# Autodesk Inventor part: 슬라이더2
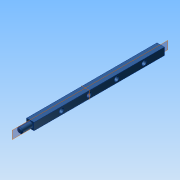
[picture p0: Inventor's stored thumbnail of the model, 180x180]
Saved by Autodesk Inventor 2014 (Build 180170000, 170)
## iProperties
Company: 한국ATC센터
Created: 2015-04
Part Number: 슬라이더2
Document SubType Name: Modeling
Designer: KYOUNG IL JANG
Density: 7.85 g/cm^3
Material: 강
Appearance: 하늘색 짙음
Author: KYOUNG IL JANG
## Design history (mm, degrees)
sketch "스케치3"
  geometry: L1 (4, 142)-(-4, 142); L2 (-4, 142)-(-4, 0); L3 (-4, 0)-(4, 0); L4 (4, 0)-(4, 142); 3 further points
  constraints: 8 end point, 2 coincident, 2 parallel, 1 horizontal, 1 midpoint, 1 perpendicular
  dimensions: "d5" = 8 distance of L1.start L1.end; "d6" = 142 distance of L1.end L2.end
extrude "돌출3" new body sketch "스케치3" stored distance "d7" = 8; taper "d8" = 0 deg
sketch "스케치4"
  geometry: L1 (8, 0)-(0, 0) reference; 3 further points
  constraints: 1 midpoint, 1 vertical alignment
  dimensions: "d9" = 30 distance of point (4, 30) point (4, 0)
hole "구멍1" sketch "스케치4" at (4, 30) diameter "d10" = 5; stored, may be unused: countersink angle "d14" = 90 deg, drill point angle "d16" = 118 deg; dims "d11" = 6, "d12" = 4, "d13" = 2, "d15" = 8
sketch "스케치5"
  geometry: C1 r 3 at (4, -4); 1 further point
  constraints: 1 centre point, 1 coincident
  dimensions: "d20" = 6 diameter of C1
extrude "돌출4" join sketch "스케치5" distance "d21" = 12; taper "d22" = 0 deg
chamfer "모따기1" distance "d23" = 1; stored, may be unused: second distance "d24" = 2, angle "d25" = 45 deg
node "작업 평면2"
  node "작업축1"
node "작업 평면3"
node "솔리드1"
pattern_linear "직사각형 패턴1" dims "d19" = 30
node "솔리드2"
other parameters: "d26" = 0
